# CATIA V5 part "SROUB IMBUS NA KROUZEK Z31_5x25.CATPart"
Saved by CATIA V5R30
Part number: SROUB IMBUS NA KROUZEK Z31/5x25
Bounding box of the stored display mesh (mm): x -5 to 25, y -4.24 to 4.24, z -4.25 to 4.25
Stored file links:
  C:\Users\ondra\Desktop\PŘÍLOHA P III\CATIA\SROUB IMBUS NA KROUZEK Z31_5x25.CATPart
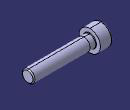
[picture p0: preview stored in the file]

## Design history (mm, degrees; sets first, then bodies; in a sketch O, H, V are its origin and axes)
Set1
  DatumSurface1 to DatumSurface29 "Z31/5x25"
  Join1: Elements (DatumSurface1; DatumSurface2; DatumSurface3; DatumSurface4; DatumSurface5; DatumSurface6; DatumSurface7; DatumSurface8; DatumSurface9; DatumSurface10; DatumSurface11; DatumSurface12; DatumSurface13; DatumSurface14; DatumSurface15; DatumSurface16; DatumSurface17; DatumSurface18; DatumSurface19; DatumSurface20; DatumSurface21; DatumSurface22; DatumSurface23; DatumSurface24; DatumSurface25; DatumSurface26; DatumSurface27; DatumSurface28; DatumSurface29)
Set2 "Geometry Failure"
  Set3 "FaceKO#Z31/5x25#409"
    DatumSurface30 "Sur409_1"
    Circle1 "Crv409_1": stored without definition
    DatumCurve1 "PCrv409_1"
    Circle2 "Crv409_2": stored without definition
    DatumCurve2 "PCrv409_2"
    Circle3 "Crv409_3": stored without definition
    DatumCurve3 "PCrv409_3"
    Circle4 "Crv409_4": stored without definition
    DatumCurve4 "PCrv409_4"
Body1 (main body)
  CloseSurface1: CloseElement Join1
